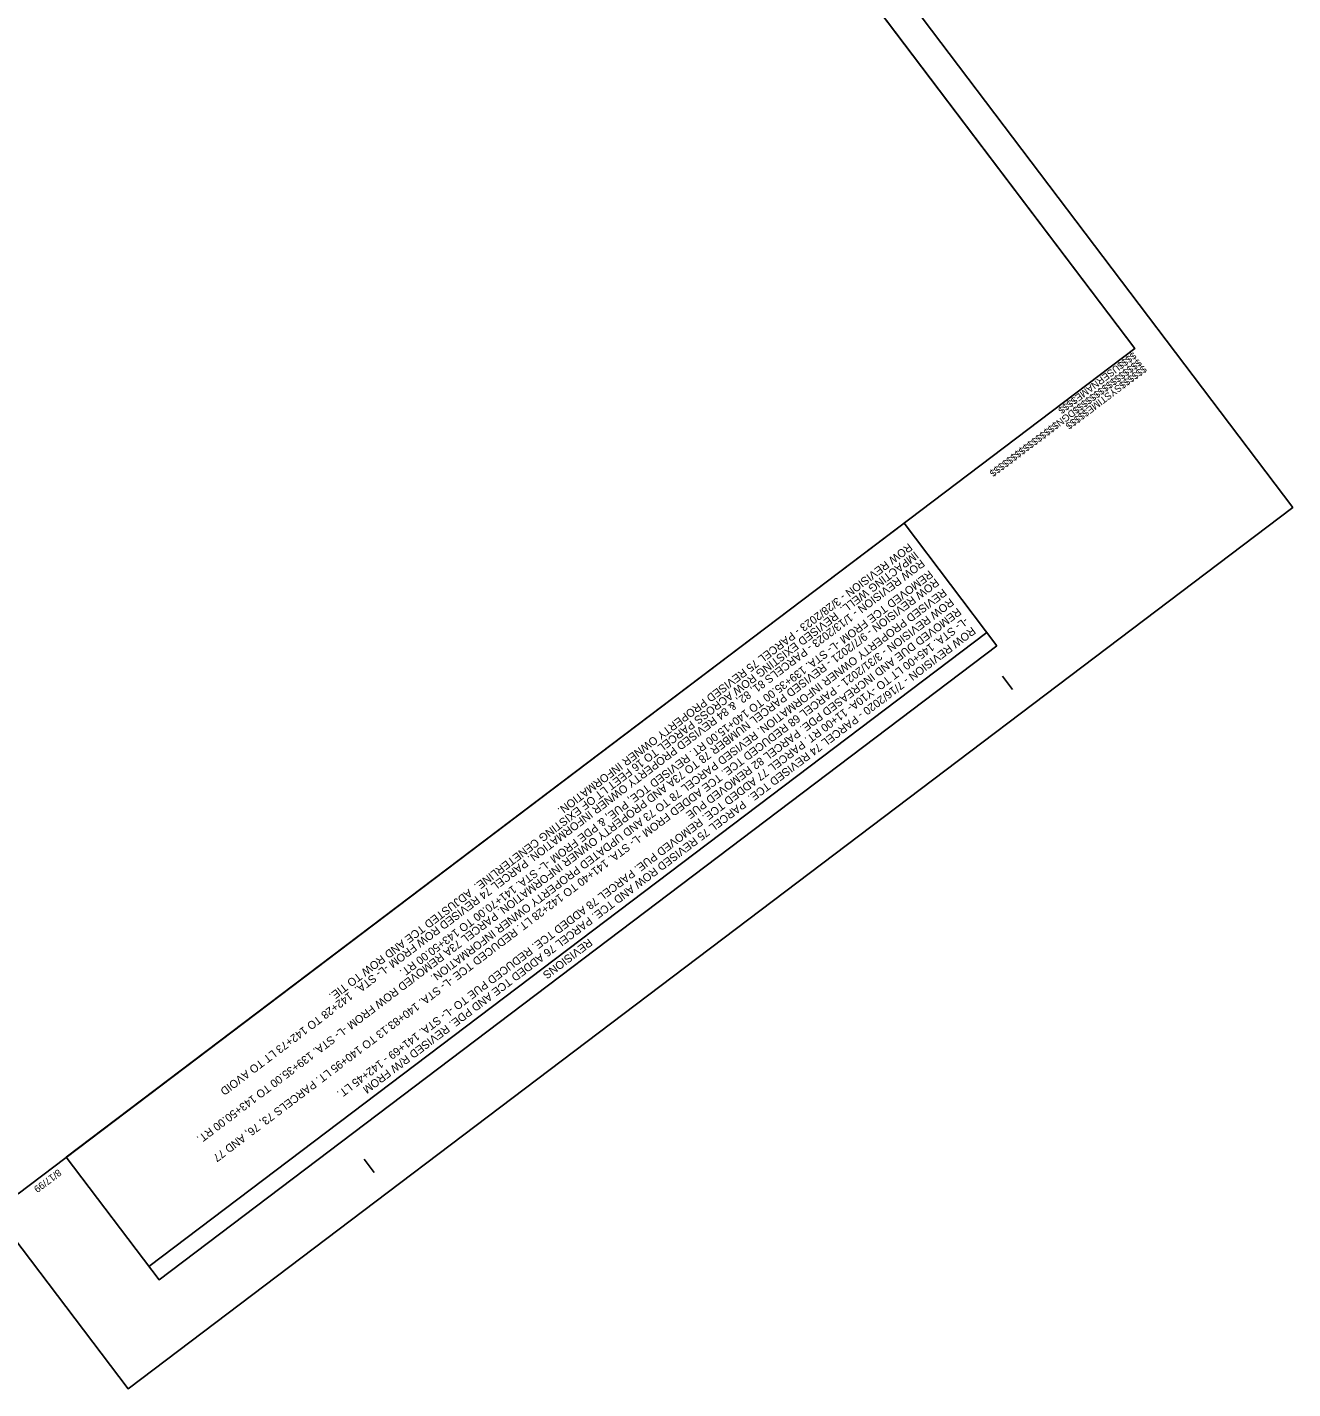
# Model space of a CAD drawing. Extents: x 475599 to 477488, y 499839 to 501843.
# Drawn here: x 476539 to 477488, y 499839 to 500860 of the extents above; entities that cross this region are included whole.
import ezdxf

# ---------------------------------------------------------------- set-up
doc = ezdxf.new("R2010")
doc.units = 0
for name, color, linetype in [('Sheet Block Revision CELL', 7, 'Continuous'), ('Sheet Layout Plan Border', 7, 'Continuous'), ('Sheet Plan CELL', 7, 'Continuous'), ('Sheet Plot Border Outside CELL', 7, 'Continuous')]:
    doc.layers.add(name, color=color, linetype=linetype)

msp = doc.modelspace()

# ---------------------------------------------------------------- linework, layer by layer
at = {"layer": 'Sheet Block Revision CELL'}
msp.add_line((477258.6, 500406.5), (476630.4, 499931), dxfattribs=at)
msp.add_lwpolyline([(477266.1, 500396.5), (476638, 499921), (476568.4, 500013), (477196.5, 500488.4)], close=True, dxfattribs=at)
at = {"layer": 'Sheet Layout Plan Border'}
msp.add_lwpolyline([(477369.5, 500619.3), (476565.1, 501682), (476503.3, 501631.1), (476482.5, 501623.3), (476353.4, 501551.6), (476353.4, 501551.6), (475928.1, 501315.2), (475798.2, 501243), (475886.1, 501126.9), (475780.9, 501047.3), (475875.9, 500921.9), (475842.7, 500896.7), (476532.3, 499985.6)], close=True, dxfattribs=at)
at = {"layer": 'Sheet Plan CELL'}
for p, q in [((477369.5, 500619.3), (477369.5, 500619.3)), ((477277.7, 500363.7), (477270.2, 500373.6)), ((476799.3, 500001.5), (476791.7, 500011.5))]:
    msp.add_line(p, q, dxfattribs=at)
for points in [[(475626.9, 501181.7), (476532.3, 499985.6), (477369.5, 500619.3), (476464.2, 501815.4)], [(477369.5, 500619.4), (476532.3, 499985.6), (475747.7, 501022.1), (475867.3, 501112.7), (475746.6, 501272.2), (476464.2, 501815.4)]]:
    msp.add_lwpolyline(points, close=True, dxfattribs=at)
at = {"layer": 'Sheet Plot Border Outside CELL'}
msp.add_lwpolyline([(476471.8, 501842.5), (477487.9, 500500.2), (476614.8, 499839.3), (475598.8, 501181.6)], close=True, dxfattribs=at)

# ---------------------------------------------------------------- texts
at = {"layer": 'Sheet Block Revision CELL'}
for s, rotation, p in [('IMPACTING WELL.  REVISED EXISTING ROW ACROSS PARCEL TO 16 FEET LT OF EXISTING CENETERLINE.  ADJUSTED TCE AND ROW TO TIE.', 217.1236, (477204.5, 500467.6)), ('ROW REVISION - 3/28/2023 - PARCEL 75 REVISED PROPERTY OWNER INFORMATION. ', 217.1236, (477199.9, 500473.7)), ('ROW REVISION - 1/13/2023 - PARCELS 81, 82, & 84 REVISED PROPERTY OWNER INFORMATION. PARCEL 74 REVISED ROW FROM -L- STA.  142+28 TO 142+73 LT TO AVOID ', 217.1236, (477209.1, 500461.6)), ('ROW REVISION - 9/7/2021 - REVISED PARCEL NUMBER 78 TO 73A AND PROPERTY OWNER INFORMATION. PARCEL 73A REMOVED ROW FROM -L- STA. 139+35.00 TO 143+50.00 RT. ', 217.1236, (477219.9, 500447.3)), ('REMOVED TCE FROM -L- STA. 139+35.00 TO 140+15.00 RT. REVISED TCE, PUE, & PDE FROM -L- STA. 141+70.00 TO 143+50.00 RT. ', 217.1236, (477215.3, 500453.4)), ('REVISED PROPERTY OWNER INFORMATION. REVISED PARCEL 78 TO 73 AND UPDATED PROPERTY OWNER INFORMATION.', 217.1236, (477225.6, 500439.7)), ('ROW REVISION - 3/31/2021 - PARCEL 68 REDUCED TCE. TCE ADDED FROM -L- STA. 141+40 TO 142+28 LT. REDUCED TCE -L- STA. 140+83.13 TO 140+95 LT. PARCELS 73, 76, AND 77 ', 217.1236, (477231, 500432.5)), ('REMOVED DUE AND INCREASED PDE. PARCEL 82 REMOVED PUE', 217.1236, (477236.5, 500425.3)), ('-L- STA. 145+00 LT TO -Y10A- 11+00 RT. PARCEL 77 ADDED TCE. REMOVED PUE. PARCEL 78 ADDED TCE. REDUCED PUE TO -L- STA. 141+69 - 142+45 LT. ', 217.1236, (477241.9, 500418.2)), ('ROW REVISION - 7/16/2020 - PARCEL 74 REVISED TCE.  PARCEL 75 REVISED ROW AND TCE. PARCEL 76 ADDED TCE AND PDE. REVISED R/W FROM', 217.1236, (477247.3, 500411)), ('REVISIONS', 217.1251, (476960, 500177.3))]:
    msp.add_text(s, height=6, rotation=rotation, dxfattribs=at).set_placement(p)
at = {"layer": 'Sheet Plan CELL'}
for s, p in [('$$$$$$$$$$$$$$$$DGN$$$$$$$$$$$$$$$$', (477372.2, 500611.8)), ('$$$$USERNAME$$$$', (477368.2, 500617)), ('$$$$$$SYSTIME$$$$$', (477375.9, 500607)), ('8/17/99', (476562.3, 500004.3))]:
    msp.add_text(s, height=5.25, rotation=217.1236, dxfattribs=at).set_placement(p)

doc.saveas('drawing.dxf')
